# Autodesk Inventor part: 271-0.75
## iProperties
Created: 2009-09
Part Number: 271-0.75
Document SubType Name: Modeling
Designer: D Cole
Density: 1 g/cm^3
Translation Standard: STEP AP214IS
File Name: P:\Fastrack\52978_CRANE\Drawings\Drawings2\271-0.75.stp
Preprocessor: Autodesk Inventor 11
Postprocessor: Build: 320, Release: 2008 SP2 - Date: Mon 11/26/2007
Sent Units: MILLIMETERS
Uncertainty: 0.01
Author: D Cole
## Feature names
1. Base1
